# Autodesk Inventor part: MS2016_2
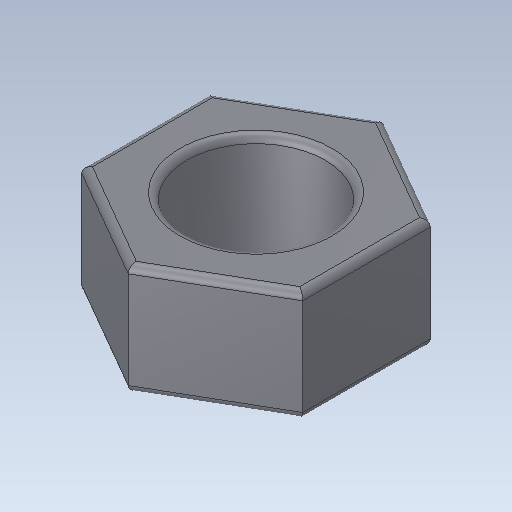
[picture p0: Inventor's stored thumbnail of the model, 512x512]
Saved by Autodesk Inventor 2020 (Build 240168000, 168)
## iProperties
Created: 2015-11
Part Number: MS2016_2
Material: Ogólny
Document SubType Name: Modeling
Designer: Tomasz
Density: 1 g/cm^3
Appearance: Domyślna
Sending System: SolidWorks 2017
Last Author: Tomasz
Last Saved: 2017-09-17
Author: Tomasz
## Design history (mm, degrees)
feature "Imported1"
node "Bryła1"
